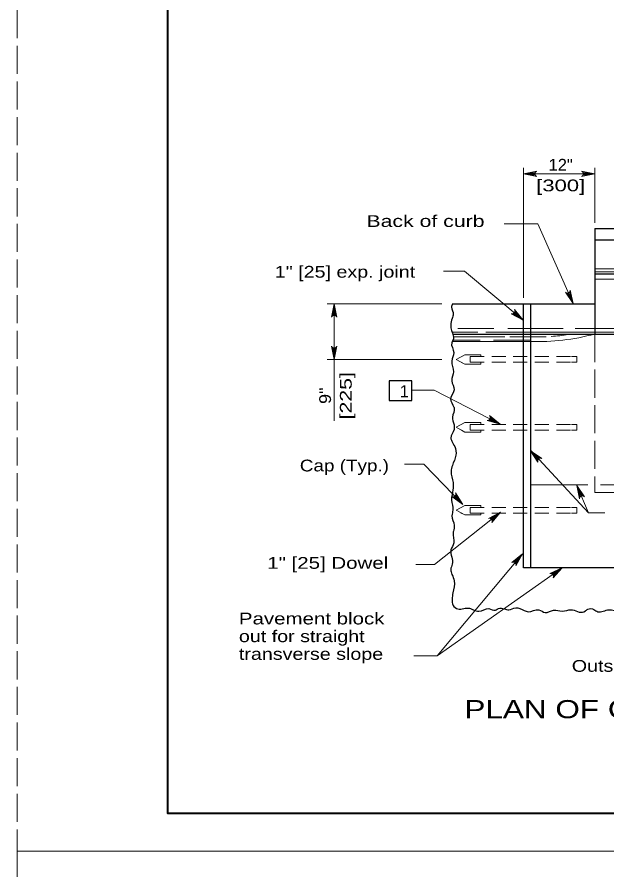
# Model space of a CAD drawing. Extents: x 1352.5 to 1386.5, y 735.9 to 779.9.
# Drawn here: x 1352.51 to 1360.33, y 757.67 to 768.97 of the extents above; entities that cross this region are included whole.
import ezdxf
from ezdxf.enums import TextEntityAlignment as Align

# ---------------------------------------------------------------- set-up
doc = ezdxf.new("R2010")
doc.units = 0
doc.header["$LTSCALE"] = 0.062
doc.linetypes.add('LONG_DASHED', pattern=[7.5, 6, -1.5])
doc.linetypes.add('MEDIUM_DASHED', pattern=[4.5, 3, -1.5])
doc.layers.add('1', color=7, linetype='Continuous', lineweight=13)

msp = doc.modelspace()

# ---------------------------------------------------------------- linework, layer by layer
at = {"layer": '1'}
for p, q in [((1359.22867, 765.25258), (1359.22867, 766.97317)), ((1360.17267, 766.24658), (1360.17267, 766.97317)), ((1359.38892, 766.91692), (1359.22867, 766.8945)), ((1359.3835, 766.90583), (1359.22867, 766.8945)), ((1359.38183, 766.8945), (1359.22867, 766.8945)), ((1359.38467, 766.88017), (1359.22867, 766.8945)), ((1359.39083, 766.86975), (1359.22867, 766.8945)), ((1359.22867, 766.8945), (1360.17267, 766.8945)), ((1360.0105, 766.86975), (1360.17267, 766.8945)), ((1360.01242, 766.91692), (1360.17267, 766.8945)), ((1360.01667, 766.88017), (1360.17267, 766.8945)), ((1360.01783, 766.90583), (1360.17267, 766.8945)), ((1360.0195, 766.8945), (1360.17267, 766.8945)), ((1360.17267, 765.63458), (1361.14133, 765.63458)), ((1360.17267, 765.59708), (1361.63583, 765.59708)), ((1359.80258, 765.31533), (1359.88775, 765.17775)), ((1359.81492, 765.31483), (1359.88775, 765.17775)), ((1359.82592, 765.31792), (1359.88775, 765.17775)), ((1359.838, 765.32625), (1359.88775, 765.17775)), ((1359.845, 765.33608), (1359.88775, 765.17775)), ((1358.14308, 765.17233), (1356.624, 765.17233)), ((1356.69358, 765.01017), (1356.71842, 765.17233)), ((1356.704, 765.01633), (1356.71842, 765.17233)), ((1356.71842, 765.17233), (1356.71842, 763.62342)), ((1356.71842, 765.01917), (1356.71842, 765.17233)), ((1356.72975, 765.0175), (1356.71842, 765.17233)), ((1356.74083, 765.01208), (1356.71842, 765.17233)), ((1359.08608, 765.04042), (1359.22283, 764.954)), ((1359.09742, 765.04533), (1359.22283, 764.954)), ((1359.106, 765.05292), (1359.22283, 764.954)), ((1359.11308, 765.06575), (1359.22283, 764.954)), ((1359.11517, 765.07767), (1359.22283, 764.954)), ((1358.2845, 764.7975), (1358.62417, 764.7975)), ((1358.35883, 764.8475), (1358.83358, 764.8475)), ((1358.72892, 764.7975), (1360.724, 764.7975)), ((1359.0195, 764.8475), (1359.75233, 764.8475)), ((1359.91117, 764.8475), (1360.5815, 764.8475)), ((1358.652, 764.69175), (1358.29258, 764.69175)), ((1358.98083, 764.73608), (1358.29692, 764.73608)), ((1359.32308, 764.69175), (1358.82925, 764.69175)), ((1359.32308, 764.73608), (1359.0485, 764.73608)), ((1356.696, 764.5955), (1356.71842, 764.43525)), ((1356.70708, 764.59008), (1356.71842, 764.43525)), ((1356.71842, 764.66583), (1356.71842, 764.43525)), ((1356.74317, 764.59733), (1356.71842, 764.43525)), ((1356.73283, 764.59125), (1356.71842, 764.43525)), ((1356.71842, 764.58842), (1356.71842, 764.43525)), ((1359.32308, 764.67258), (1358.284, 764.67258)), ((1358.44983, 764.49767), (1358.40933, 764.47567)), ((1358.44983, 764.49767), (1358.52575, 764.49767)), ((1358.52067, 764.39775), (1358.52067, 764.47275)), ((1358.66225, 764.47275), (1358.66225, 764.49767)), ((1359.93667, 764.47275), (1359.86542, 764.47275)), ((1359.93667, 764.47275), (1359.93667, 764.39775)), ((1358.14308, 764.43525), (1356.624, 764.43525)), ((1358.44983, 764.37275), (1358.40742, 764.39583)), ((1358.44983, 764.37275), (1358.56217, 764.37275)), ((1358.66225, 764.39775), (1358.66225, 764.37275)), ((1359.93667, 764.39775), (1359.86542, 764.39775)), ((1358.78742, 763.67442), (1358.92042, 763.57833)), ((1358.78817, 763.66233), (1358.92042, 763.57833)), ((1358.44983, 763.59825), (1358.41158, 763.57742)), ((1358.44983, 763.59825), (1358.5555, 763.59825)), ((1358.52067, 763.49825), (1358.52067, 763.57325)), ((1358.66225, 763.57325), (1358.66225, 763.59825)), ((1358.76758, 763.6315), (1358.92042, 763.57833)), ((1358.7775, 763.63892), (1358.92042, 763.57833)), ((1358.78408, 763.64825), (1358.92042, 763.57833)), ((1359.93667, 763.57325), (1359.86542, 763.57325)), ((1359.93667, 763.57325), (1359.93667, 763.49825)), ((1358.44983, 763.47333), (1358.40683, 763.49667)), ((1358.44983, 763.47333), (1358.5555, 763.47333)), ((1358.66225, 763.49825), (1358.66225, 763.47333)), ((1359.93667, 763.49825), (1359.86542, 763.49825)), ((1359.42858, 763.11633), (1359.32158, 763.22592)), ((1359.42025, 763.10425), (1359.32158, 763.22592)), ((1359.41708, 763.09258), (1359.32158, 763.22592)), ((1359.43783, 763.123), (1359.32158, 763.22592)), ((1359.44958, 763.12692), (1359.32158, 763.22592)), ((1360.09033, 762.40192), (1359.32308, 763.22708)), ((1359.32308, 762.77367), (1360.08217, 762.77367)), ((1359.993, 762.62367), (1359.93525, 762.76558)), ((1359.98075, 762.61567), (1359.93525, 762.76558)), ((1359.97342, 762.60608), (1359.93525, 762.76558)), ((1360.00408, 762.62642), (1359.93525, 762.76558)), ((1360.01642, 762.62558), (1359.93525, 762.76558)), ((1360.24875, 762.77367), (1361.10942, 762.77367)), ((1358.33025, 762.64875), (1358.42433, 762.51442)), ((1358.29742, 762.61483), (1358.42433, 762.51442)), ((1358.30917, 762.61858), (1358.42433, 762.51442)), ((1358.3185, 762.62517), (1358.42433, 762.51442)), ((1358.32692, 762.63717), (1358.42433, 762.51442)), ((1358.44983, 762.49883), (1358.40983, 762.47708)), ((1358.44983, 762.49883), (1358.55225, 762.49883)), ((1358.52067, 762.39892), (1358.52067, 762.47383)), ((1358.66225, 762.47383), (1358.66225, 762.49883)), ((1359.93667, 762.47383), (1359.86542, 762.47383)), ((1359.93667, 762.47383), (1359.93667, 762.39892)), ((1358.44983, 762.37392), (1358.394, 762.40433)), ((1358.44983, 762.37392), (1358.55225, 762.37392)), ((1358.66225, 762.39892), (1358.66225, 762.37392)), ((1358.7815, 762.32925), (1358.92467, 762.40925)), ((1358.79275, 762.32483), (1358.92467, 762.40925)), ((1358.80383, 762.31517), (1358.92467, 762.40925)), ((1358.80942, 762.30525), (1358.92467, 762.40925)), ((1358.812, 762.29317), (1358.92467, 762.40925)), ((1359.93667, 762.39892), (1359.86542, 762.39892)), ((1359.0915, 761.74933), (1359.21408, 761.85825)), ((1359.10342, 761.74742), (1359.21408, 761.85825)), ((1359.11625, 761.74042), (1359.21408, 761.85825)), ((1359.12392, 761.73192), (1359.21408, 761.85825)), ((1359.129, 761.72067), (1359.21408, 761.85825)), ((1359.59608, 761.59675), (1359.74142, 761.67283)), ((1359.60717, 761.592), (1359.74142, 761.67283)), ((1359.618, 761.58208), (1359.74142, 761.67283)), ((1359.62333, 761.572), (1359.74142, 761.67283)), ((1359.62558, 761.55983), (1359.74142, 761.67283)), ((1358.08192, 760.50925), (1357.77175, 760.50925))]:
    msp.add_line(p, q, dxfattribs=at)
at = {"layer": '1', "lineweight": 25}
for p, q in [((1360.17267, 766.17175), (1360.17267, 764.77258)), ((1360.17267, 766.17175), (1365.83667, 766.17175)), ((1360.17267, 766.02183), (1365.83667, 766.02183)), ((1360.17267, 765.57208), (1365.83667, 765.57208)), ((1358.28467, 765.17233), (1360.17267, 765.17233)), ((1359.32308, 764.03883), (1359.32308, 765.17233)), ((1358.29033, 764.77258), (1364.77742, 764.77258)), ((1359.32308, 762.87167), (1359.32308, 764.03883)), ((1359.32308, 762.02633), (1359.32308, 762.87167)), ((1359.32308, 761.67433), (1359.32308, 762.02633))]:
    msp.add_line(p, q, dxfattribs=at)
at = {"layer": '1', "linetype": 'LONG_DASHED'}
for p, q in [((1360.17267, 765.49717), (1365.83667, 765.49717)), ((1360.17267, 764.77258), (1360.17267, 762.67375)), ((1360.17267, 762.67375), (1364.50358, 762.67375))]:
    msp.add_line(p, q, dxfattribs=at)
at = {"layer": '1', "linetype": 'MEDIUM_DASHED'}
for p, q in [((1358.33492, 764.43525), (1358.44983, 764.49767)), ((1358.66225, 764.49767), (1358.44983, 764.49767)), ((1358.52067, 764.47275), (1359.93667, 764.47275)), ((1358.33492, 764.43525), (1358.44983, 764.37275)), ((1358.66225, 764.37275), (1358.44983, 764.37275)), ((1358.52067, 764.39775), (1359.93667, 764.39775)), ((1358.33492, 763.53575), (1358.44983, 763.59825)), ((1358.66225, 763.59825), (1358.44983, 763.59825)), ((1358.52067, 763.57325), (1359.93667, 763.57325)), ((1358.33492, 763.53575), (1358.44983, 763.47333)), ((1358.66225, 763.47333), (1358.44983, 763.47333)), ((1358.52067, 763.49825), (1359.93667, 763.49825)), ((1358.33492, 762.43642), (1358.44983, 762.49883)), ((1358.33492, 762.43642), (1358.44983, 762.37392)), ((1358.66225, 762.49883), (1358.44983, 762.49883)), ((1358.52067, 762.47383), (1359.93667, 762.47383)), ((1358.66225, 762.37392), (1358.44983, 762.37392)), ((1358.52067, 762.39892), (1359.93667, 762.39892))]:
    msp.add_line(p, q, dxfattribs=at)
at = {"layer": '1', "linetype": 'LONG_DASHED'}
for points in [[(1352.513, 757.91967), (1386.513, 757.91967), (1386.513, 779.91967), (1352.513, 779.91967)], [(1352.513, 735.91967), (1386.513, 735.91967), (1386.513, 757.91967), (1352.513, 757.91967)]]:
    msp.add_lwpolyline(points, close=True, dxfattribs=at)
at = {"layer": '1', "lineweight": 25}
for points in [[(1386.013, 758.41967), (1354.513, 758.41967), (1354.513, 779.41967)], [(1366.78067, 761.67433), (1359.22867, 761.67433), (1359.22867, 765.17233)]]:
    msp.add_lwpolyline(points, dxfattribs=at)
at = {"layer": '1', "lineweight": 40}
msp.add_lwpolyline([(1354.513, 779.41967), (1386.013, 779.41967), (1386.013, 758.41967), (1354.513, 758.41967)], close=True, dxfattribs=at)
msp.add_lwpolyline([(1354.513, 779.41967), (1386.013, 779.41967), (1386.013, 758.41967), (1354.513, 758.41967)], close=True, dxfattribs=at)
at = {"layer": '1'}
for points in [[(1359.40567, 766.85908), (1359.22867, 766.8945), (1359.40567, 766.92992)], [(1359.99567, 766.85908), (1360.17267, 766.8945), (1359.99567, 766.92992)], [(1358.97275, 766.23225), (1359.41858, 766.23225), (1359.88775, 765.17775)], [(1359.22283, 764.954), (1358.44767, 765.6065), (1358.16933, 765.6065)], [(1359.84875, 765.354), (1359.88775, 765.17775), (1359.78392, 765.32542)], [(1356.683, 764.99533), (1356.71842, 765.17233), (1356.75383, 764.99533)], [(1359.11067, 765.09533), (1359.22283, 764.954), (1359.06492, 765.04133)], [(1356.75383, 764.61225), (1356.71842, 764.43525), (1356.683, 764.61225)], [(1358.92042, 763.57833), (1358.04417, 764.02925), (1357.7495, 764.02925)], [(1358.77908, 763.69058), (1358.92042, 763.57833), (1358.74675, 763.62767)], [(1359.41992, 763.0745), (1359.32158, 763.22592), (1359.47058, 763.12392)], [(1358.42433, 762.51442), (1357.90458, 763.04742), (1357.64867, 763.04742)], [(1360.3075, 762.40192), (1360.09033, 762.40192), (1359.93525, 762.76558)], [(1359.96917, 762.58825), (1359.93525, 762.76558), (1360.03475, 762.615)], [(1358.32758, 762.66683), (1358.42433, 762.51442), (1358.27642, 762.61792)], [(1358.92467, 762.40925), (1358.05008, 761.7195), (1357.80158, 761.7195)], [(1358.76325, 762.3285), (1358.92467, 762.40925), (1358.80675, 762.27258)], [(1359.21408, 761.85825), (1358.08192, 760.50925), (1359.74142, 761.67283)], [(1359.07383, 761.74467), (1359.21408, 761.85825), (1359.12825, 761.6995)], [(1359.57783, 761.5965), (1359.74142, 761.67283), (1359.61975, 761.5395)]]:
    msp.add_lwpolyline(points, dxfattribs=at)
at = {"layer": '1', "lineweight": 25}
msp.add_lwpolyline([(1357.44883, 764.15317), (1357.44883, 763.8915), (1357.74767, 763.8915), (1357.74767, 764.15317)], close=True, dxfattribs=at)
at = {"layer": '1'}
for centre, start, end in [((1359.41997, 766.89456), 112.08782, 247.91395), ((1359.98138, 766.89456), 292.08605, 67.91218), ((1359.81052, 765.35275), 225.88897, 1.7151), ((1356.71847, 764.98102), 22.08782, 157.91395), ((1359.07684, 765.07756), 251.82809, 27.65422), ((1356.7184, 764.62654), 202.08782, 337.91395), ((1358.75016, 763.66562), 264.92977, 40.75589), ((1359.45527, 763.08906), 66.38829, 202.21442), ((1358.29213, 762.65272), 245.79093, 21.61706), ((1360.00742, 762.58839), 44.24031, 180.06643), ((1358.77373, 762.29176), 329.96819, 105.79432), ((1359.09195, 761.71106), 342.39823, 118.22436), ((1359.58729, 761.55948), 328.41662, 104.24275)]:
    msp.add_arc(centre, 0.0382, start, end, dxfattribs=at)
for major_axis, start_param, end_param in [((0, -3.24194), 6.25380565, 6.53387946), ((0, -3.17847), 6.25380565, 6.32168635), ((0, -3.17847), 0.06100488, 0.13668071)]:
    msp.add_ellipse((1359.41303, 767.91314), major_axis=major_axis, ratio=0.944544, start_param=start_param, end_param=end_param, dxfattribs=at)
at = {"layer": '1', "lineweight": 25}
msp.add_spline([(1358.28467, 765.17233), (1358.27392, 765.12667), (1358.2975, 765.03625), (1358.28183, 764.97875), (1358.263, 764.8895), (1358.2955, 764.75042), (1358.29975, 764.70767), (1358.27567, 764.65417), (1358.30367, 764.527), (1358.276, 764.413), (1358.29917, 764.27292), (1358.27708, 764.15292), (1358.308, 764.03467), (1358.2615, 763.91375), (1358.30475, 763.80333), (1358.30933, 763.79042), (1358.28633, 763.67242), (1358.307, 763.56908), (1358.30733, 763.5055), (1358.26458, 763.39358), (1358.2765, 763.35383), (1358.31542, 763.28217), (1358.33125, 763.166), (1358.2845, 763.03125), (1358.26858, 762.95183), (1358.2935, 762.80483), (1358.2925, 762.70558), (1358.27417, 762.57167), (1358.29075, 762.43958), (1358.27958, 762.36417), (1358.30842, 762.236), (1358.29917, 762.16067), (1358.29425, 762.13983), (1358.30233, 762.00375), (1358.26642, 761.91058), (1358.28425, 761.722), (1358.26283, 761.65158), (1358.28, 761.586), (1358.3085, 761.50242), (1358.29175, 761.34075), (1358.2805, 761.25842), (1358.29475, 761.17592), (1358.35658, 761.13), (1358.51342, 761.13717), (1358.55292, 761.12108), (1358.56608, 761.11508), (1358.63575, 761.09783), (1358.76925, 761.133), (1358.85692, 761.11367), (1358.89675, 761.13533), (1358.97408, 761.129), (1359.03258, 761.11875), (1359.12533, 761.14317), (1359.181, 761.13592), (1359.29192, 761.09167), (1359.431, 761.11583), (1359.51567, 761.08167), (1359.62733, 761.11192), (1359.73958, 761.09942), (1359.86158, 761.11775), (1359.87758, 761.11667), (1359.968, 761.08742), (1360.04842, 761.10192), (1360.08075, 761.12558), (1360.16192, 761.12125), (1360.21442, 761.09217), (1360.28625, 761.09775), (1360.36108, 761.11825), (1360.50533, 761.09767), (1360.6295, 761.13883), (1360.74825, 761.12333), (1360.84658, 761.13875), (1360.96342, 761.10742), (1361.01933, 761.13), (1361.08833, 761.13558), (1361.15683, 761.0975), (1361.255, 761.08808), (1361.27867, 761.09392), (1361.43375, 761.122), (1361.49517, 761.11967), (1361.53275, 761.10167), (1361.57025, 761.08258), (1361.784, 761.11633), (1361.85842, 761.09508), (1362.07767, 761.11092), (1362.13883, 761.09375), (1362.31467, 761.11475), (1362.37792, 761.11242), (1362.4625, 761.07225), (1362.54092, 761.07883), (1362.56267, 761.08175), (1362.68658, 761.099), (1362.80325, 761.06467), (1363.02833, 761.09833), (1363.14808, 761.08083), (1363.22175, 761.07458), (1363.42808, 761.12617)], degree=3, dxfattribs=at)

# ---------------------------------------------------------------- texts
at = {"layer": '1'}
for s, width, p in [('12"', 1.05, (1359.72117, 766.93758)), ('[300]', 1.4, (1359.72117, 766.66358)), ('1" [25] exp. joint', 1.25, (1356.86112, 765.519))]:
    msp.add_text(s, height=0.156, dxfattribs=dict(at, width=width)).set_placement(p, align=Align.CENTER)
for s, height, width, p in [('Back of curb', 0.156, 1.35, (1357.146, 766.19125)), ('Cap (Typ.)', 0.156, 1.2, (1356.26233, 762.95158)), ('1" [25] Dowel', 0.156, 1.3, (1355.83067, 761.66058)), ('Pavement block', 0.156, 1.3, (1355.45458, 760.9235)), ('out for straight', 0.156, 1.25, (1355.45458, 760.68883)), ('transverse slope', 0.156, 1.25, (1355.45458, 760.45417)), ('Outside of conc. basin', 0.156, 1.25, (1359.86817, 760.29575)), ('PLAN OF CATCH BASIN AND PAVEMENT JOINTS', 0.24, 1.3, (1358.44475, 759.68083))]:
    msp.add_text(s, height=height, dxfattribs=dict(at, width=width)).set_placement(p)
for s, width, p in [('[225]', 1.35, (1356.95008, 763.95425)), ('9"', 1.15, (1356.67608, 763.95425))]:
    msp.add_text(s, height=0.156, rotation=90, dxfattribs=dict(at, width=width)).set_placement(p, align=Align.CENTER)
msp.add_text('1', height=0.16, dxfattribs=at).set_placement((1357.58767, 763.93392))

doc.saveas('drawing.dxf')
